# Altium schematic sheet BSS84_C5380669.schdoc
size 127 x 101 mm
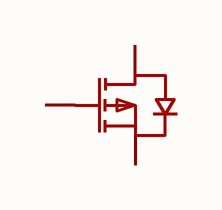
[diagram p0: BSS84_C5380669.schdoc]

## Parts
Q?  bss84_c5380669  [SOT-23-3_L2.9-W1.3-P1.90-LS2.4-BR]  (value not drawn)

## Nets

Not connected (* = marked no-connect by the designer): Q? 1(G) 2(S) 3(D)

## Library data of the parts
Q? = bss84_c5380669: 漏源电压(Vdss):50V;连续漏极电流(Id):130mA;耗散功率(Pd):225mW;阈值电压(Vgs(th)):2V;; Manufacturer: TECH PUBLIC(台舟); ManufacturerPart: BSS84; AddInBom: yes; ModelId: c62791f0466c4ae2a892c056b845b0ca; ModelName: SOT-23-3P_L2.9-W1.3-H1.0-LS2.4-P0.95; ModelTransform: 98.425,114.173,0,180,0,0,0.0005,-0.0005,0; Drain to Source Voltage: 50V; Current - Continuous Drain(Id): 130mA; Pd - Power Dissipation: 225mW; Gate Threshold Voltage (Vgs(th)@Id): 2V; Input Capacitance(Ciss@Vds): 30pF@5V; Reverse Transfer Capacitance (Crss@Vds): 5pF@5V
